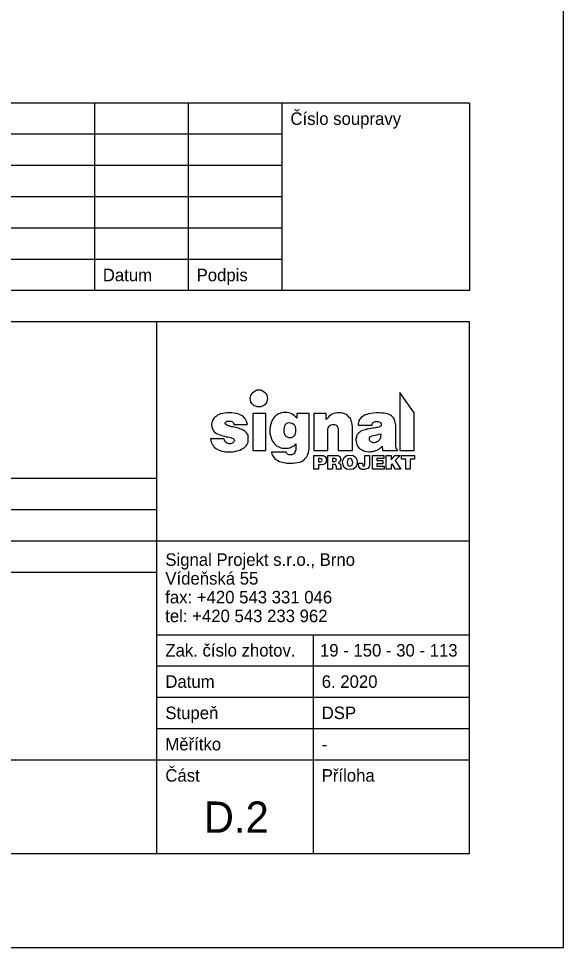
# Model space of a CAD drawing. Extents: x -790471 to -790261, y -988964 to -988667.
# Drawn here: x -790347.7 to -790260.6, y -988964.2 to -988815.7 of the extents above; entities that cross this region are included whole.
import ezdxf

# ---------------------------------------------------------------- set-up
doc = ezdxf.new("R2010")
doc.units = 0
for name, color, linetype in [('Info o rozpiskách', 7, 'Continuous'), ('popis', 7, 'Continuous'), ('Ramečky', 7, 'Continuous'), ('Rámečky-tisk', 7, 'Continuous'), ('Text', 7, 'Continuous'), ('Text barevný', 7, 'Continuous')]:
    doc.layers.add(name, color=color, linetype=linetype)

msp = doc.modelspace()

# ---------------------------------------------------------------- linework, layer by layer
at = {"layer": 'Info o rozpiskách'}
for points in [[(-790309.25, -988875.05), (-790308.98, -988875.07), (-790308.76, -988875.16), (-790308.54, -988875.29), (-790308.29, -988875.46), (-790308.15, -988875.66), (-790308.03, -988875.91), (-790307.94, -988876.17), (-790307.92, -988876.43), (-790307.94, -988876.69), (-790308.03, -988876.97), (-790308.15, -988877.21), (-790308.29, -988877.38), (-790308.54, -988877.59), (-790308.76, -988877.68), (-790308.98, -988877.77), (-790309.25, -988877.79), (-790309.54, -988877.77), (-790309.79, -988877.68), (-790310.05, -988877.59), (-790310.23, -988877.38), (-790310.4, -988877.21), (-790310.57, -988876.97), (-790310.65, -988876.69), (-790310.7, -988876.43), (-790310.65, -988876.17), (-790310.57, -988875.91), (-790310.4, -988875.66), (-790310.23, -988875.46), (-790310.05, -988875.29), (-790309.79, -988875.16), (-790309.54, -988875.07), (-790309.25, -988875.05)], [(-790300.48, -988885.53), (-790299.41, -988885.53), (-790299, -988885.57), (-790298.7, -988885.72), (-790298.52, -988885.96), (-790298.46, -988886.32), (-790298.65, -988886.84), (-790298.95, -988887.01), (-790299.38, -988887.06), (-790299.75, -988887.06), (-790299.75, -988887.75), (-790300.48, -988887.75), (-790300.48, -988885.53)], [(-790299.75, -988886.04), (-790299.75, -988886.54), (-790299.43, -988886.54), (-790299.25, -988886.48), (-790299.15, -988886.28), (-790299.23, -988886.11), (-790299.54, -988886.04), (-790299.75, -988886.04)], [(-790298.24, -988885.53), (-790297.16, -988885.53), (-790296.67, -988885.57), (-790296.35, -988885.72), (-790296.19, -988886.17), (-790296.3, -988886.52), (-790296.56, -988886.71), (-790296.24, -988886.93), (-790296.19, -988887.3), (-790296.19, -988887.47), (-790296.17, -988887.64), (-790296.11, -988887.7), (-790296.11, -988887.75), (-790296.86, -988887.75), (-790296.9, -988887.36), (-790297.03, -988887.01), (-790297.18, -988886.99), (-790297.4, -988886.97), (-790297.51, -988886.97), (-790297.51, -988887.75), (-790298.24, -988887.75), (-790298.24, -988885.53)], [(-790297.51, -988886.04), (-790297.51, -988886.48), (-790297.19, -988886.48), (-790296.93, -988886.41), (-790296.88, -988886.28), (-790296.95, -988886.11), (-790297.16, -988886.04), (-790297.51, -988886.04)], [(-790294.73, -988885.48), (-790294.23, -988885.55), (-790293.84, -988885.81), (-790293.63, -988886.19), (-790293.56, -988886.61), (-790293.63, -988887.08), (-790293.85, -988887.45), (-790294.23, -988887.72), (-790294.73, -988887.81), (-790295.25, -988887.72), (-790295.65, -988887.44), (-790295.83, -988887.06), (-790295.91, -988886.61), (-790295.83, -988886.17), (-790295.61, -988885.81), (-790295.23, -988885.55), (-790294.73, -988885.48)], [(-790294.73, -988886.02), (-790294.92, -988886.06), (-790295.05, -988886.17), (-790295.16, -988886.63), (-790295.05, -988887.12), (-790294.73, -988887.27), (-790294.38, -988887.08), (-790294.28, -988886.67), (-790294.4, -988886.2), (-790294.53, -988886.06), (-790294.73, -988886.02)], [(-790292.33, -988885.53), (-790291.6, -988885.53), (-790291.6, -988886.91), (-790291.67, -988887.34), (-790291.88, -988887.64), (-790292.46, -988887.81), (-790292.83, -988887.77), (-790293.11, -988887.62), (-790293.29, -988887.34), (-790293.37, -988886.95), (-790293.35, -988886.78), (-790292.7, -988886.78), (-790292.66, -988887.16), (-790292.51, -988887.27), (-790292.38, -988887.19), (-790292.33, -988887.01), (-790292.33, -988885.53)], [(-790291.13, -988885.53), (-790289.32, -988885.53), (-790289.32, -988886.04), (-790290.4, -988886.04), (-790290.4, -988886.37), (-790289.49, -988886.37), (-790289.49, -988886.89), (-790290.4, -988886.89), (-790290.4, -988887.23), (-790289.27, -988887.23), (-790289.27, -988887.75), (-790291.13, -988887.75), (-790291.13, -988885.53)], [(-790288.91, -988885.53), (-790288.16, -988885.53), (-790288.16, -988886.24), (-790287.53, -988885.53), (-790286.67, -988885.53), (-790287.49, -988886.37), (-790286.58, -988887.75), (-790287.46, -988887.75), (-790288, -988886.88), (-790288.16, -988887.04), (-790288.16, -988887.75), (-790288.91, -988887.75), (-790288.91, -988885.53)], [(-790286.47, -988885.53), (-790284.41, -988885.53), (-790284.41, -988886.11), (-790285.07, -988886.11), (-790285.07, -988887.75), (-790285.8, -988887.75), (-790285.8, -988886.11), (-790286.47, -988886.11), (-790286.47, -988885.53)]]:
    msp.add_lwpolyline(points, dxfattribs=at)
at = {"layer": 'popis'}
for points in [[(-790286.77, -988875.46), (-790286.77, -988884.73), (-790284.45, -988884.73), (-790284.45, -988878.7), (-790286.77, -988875.46)], [(-790313.29, -988880.61), (-790311.09, -988880.61), (-790311.15, -988880.42), (-790311.19, -988880.25), (-790311.24, -988880.09), (-790311.32, -988879.92), (-790311.41, -988879.77), (-790311.52, -988879.6), (-790311.63, -988879.45), (-790311.8, -988879.28), (-790311.97, -988879.19), (-790312.17, -988879.08), (-790312.4, -988878.98), (-790312.66, -988878.89), (-790312.94, -988878.83), (-790313.26, -988878.78), (-790313.61, -988878.74), (-790314, -988878.72), (-790314.4, -988878.74), (-790314.77, -988878.78), (-790315.09, -988878.85), (-790315.4, -988878.91), (-790315.66, -988879), (-790315.89, -988879.11), (-790316.07, -988879.25), (-790316.26, -988879.38), (-790316.43, -988879.53), (-790316.54, -988879.67), (-790316.65, -988879.82), (-790316.71, -988879.99), (-790316.78, -988880.18), (-790316.82, -988880.35), (-790316.86, -988880.48), (-790316.86, -988880.68), (-790316.8, -988880.98), (-790316.71, -988881.28), (-790316.62, -988881.5), (-790316.43, -988881.75), (-790316.26, -988881.88), (-790316.06, -988882.04), (-790315.81, -988882.16), (-790315.55, -988882.23), (-790315.29, -988882.32), (-790315.03, -988882.4), (-790314.77, -988882.47), (-790314.51, -988882.55), (-790314.25, -988882.58), (-790314.02, -988882.62), (-790313.8, -988882.68), (-790313.59, -988882.77), (-790313.39, -988882.85), (-790313.29, -988882.92), (-790313.22, -988883.01), (-790313.2, -988883.11), (-790313.24, -988883.28), (-790313.29, -988883.35), (-790313.33, -988883.44), (-790313.44, -988883.52), (-790313.57, -988883.59), (-790313.67, -988883.63), (-790313.8, -988883.67), (-790313.93, -988883.67), (-790314.06, -988883.67), (-790314.21, -988883.63), (-790314.38, -988883.57), (-790314.47, -988883.52), (-790314.6, -988883.39), (-790314.69, -988883.28), (-790314.77, -988883.09), (-790314.82, -988882.87), (-790317.01, -988882.87), (-790316.97, -988883.16), (-790316.9, -988883.42), (-790316.8, -988883.65), (-790316.69, -988883.83), (-790316.56, -988884.02), (-790316.41, -988884.19), (-790316.24, -988884.36), (-790316.06, -988884.49), (-790315.83, -988884.6), (-790315.61, -988884.71), (-790315.38, -988884.79), (-790315.14, -988884.86), (-790314.86, -988884.88), (-790314.62, -988884.94), (-790314.38, -988884.95), (-790314.06, -988884.95), (-790313.74, -988884.94), (-790313.43, -988884.94), (-790313.13, -988884.88), (-790312.83, -988884.82), (-790312.55, -988884.77), (-790312.31, -988884.67), (-790312.06, -988884.54), (-790311.86, -988884.45), (-790311.65, -988884.32), (-790311.47, -988884.15), (-790311.34, -988884), (-790311.2, -988883.83), (-790311.09, -988883.65), (-790311.02, -988883.42), (-790311, -988883.2), (-790311, -988882.98), (-790311, -988882.92), (-790311, -988882.87), (-790311, -988882.81), (-790311, -988882.75), (-790311, -988882.68), (-790311, -988882.62), (-790311, -988882.58), (-790311, -988882.55), (-790311.02, -988882.3), (-790311.11, -988882.12), (-790311.24, -988881.93), (-790311.39, -988881.8), (-790311.54, -988881.67), (-790311.73, -988881.52), (-790311.9, -988881.43), (-790312.12, -988881.35), (-790312.32, -988881.28), (-790312.55, -988881.2), (-790312.77, -988881.13), (-790312.98, -988881.09), (-790313.22, -988881.04), (-790313.43, -988880.98), (-790313.65, -988880.94), (-790313.84, -988880.89), (-790314.02, -988880.81), (-790314.19, -988880.78), (-790314.32, -988880.7), (-790314.45, -988880.66), (-790314.53, -988880.61), (-790314.64, -988880.53), (-790314.67, -988880.48), (-790314.67, -988880.4), (-790314.67, -988880.33), (-790314.64, -988880.25), (-790314.56, -988880.18), (-790314.49, -988880.14), (-790314.41, -988880.07), (-790314.28, -988880.07), (-790314.13, -988880.03), (-790314, -988880.03), (-790313.85, -988880.03), (-790313.72, -988880.07), (-790313.61, -988880.09), (-790313.5, -988880.14), (-790313.43, -988880.23), (-790313.39, -988880.33), (-790313.31, -988880.44), (-790313.29, -988880.61)], [(-790310.27, -988878.85), (-790310.27, -988884.73), (-790308.18, -988884.73), (-790308.18, -988878.85), (-790310.27, -988878.85)], [(-790303.24, -988878.83), (-790303.24, -988879.56), (-790303.41, -988879.36), (-790303.59, -988879.19), (-790303.8, -988879.02), (-790304.04, -988878.87), (-790304.28, -988878.76), (-790304.51, -988878.7), (-790304.75, -988878.67), (-790305.03, -988878.65), (-790305.29, -988878.67), (-790305.48, -988878.69), (-790305.74, -988878.72), (-790305.93, -988878.82), (-790306.15, -988878.87), (-790306.35, -988879.02), (-790306.58, -988879.13), (-790306.76, -988879.32), (-790306.91, -988879.51), (-790307.06, -988879.75), (-790307.19, -988879.99), (-790307.29, -988880.23), (-790307.4, -988880.55), (-790307.47, -988880.89), (-790307.51, -988881.26), (-790307.51, -988881.65), (-790307.51, -988881.97), (-790307.47, -988882.25), (-790307.4, -988882.51), (-790307.32, -988882.79), (-790307.23, -988883.03), (-790307.1, -988883.28), (-790306.93, -988883.48), (-790306.78, -988883.67), (-790306.62, -988883.83), (-790306.45, -988883.98), (-790306.22, -988884.11), (-790306, -988884.21), (-790305.78, -988884.3), (-790305.53, -988884.36), (-790305.29, -988884.39), (-790305.03, -988884.39), (-790304.81, -988884.39), (-790304.6, -988884.36), (-790304.34, -988884.32), (-790304.12, -988884.23), (-790303.91, -988884.13), (-790303.7, -988884), (-790303.56, -988883.87), (-790303.39, -988883.69), (-790303.39, -988884.23), (-790303.39, -988884.62), (-790303.46, -988884.88), (-790303.56, -988885.08), (-790303.63, -988885.23), (-790303.76, -988885.35), (-790303.91, -988885.38), (-790304.08, -988885.44), (-790304.26, -988885.44), (-790304.36, -988885.44), (-790304.49, -988885.42), (-790304.6, -988885.38), (-790304.69, -988885.35), (-790304.75, -988885.27), (-790304.84, -988885.2), (-790304.86, -988885.12), (-790304.9, -988885.03), (-790307.27, -988885.03), (-790307.21, -988885.33), (-790307.1, -988885.53), (-790306.97, -988885.76), (-790306.84, -988885.92), (-790306.67, -988886.13), (-790306.45, -988886.24), (-790306.24, -988886.33), (-790306, -988886.48), (-790305.78, -988886.56), (-790305.53, -988886.61), (-790305.31, -988886.67), (-790305.05, -988886.73), (-790304.84, -988886.75), (-790304.66, -988886.76), (-790304.43, -988886.78), (-790304.26, -988886.78), (-790303.85, -988886.76), (-790303.46, -988886.73), (-790303.09, -988886.67), (-790302.79, -988886.6), (-790302.49, -988886.5), (-790302.23, -988886.37), (-790302.03, -988886.22), (-790301.86, -988886.04), (-790301.69, -988885.83), (-790301.56, -988885.61), (-790301.45, -988885.37), (-790301.35, -988885.08), (-790301.32, -988884.79), (-790301.22, -988884.45), (-790301.22, -988884.1), (-790301.22, -988883.69), (-790301.22, -988878.83), (-790303.24, -988878.83)], [(-790300.5, -988878.85), (-790300.5, -988884.73), (-790298.26, -988884.73), (-790298.26, -988881.73), (-790298.26, -988881.41), (-790298.2, -988881.11), (-790298.11, -988880.94), (-790298.03, -988880.79), (-790297.9, -988880.7), (-790297.75, -988880.63), (-790297.57, -988880.61), (-790297.38, -988880.57), (-790297.19, -988880.61), (-790297.06, -988880.64), (-790296.9, -988880.7), (-790296.8, -988880.81), (-790296.73, -988880.94), (-790296.65, -988881.11), (-790296.62, -988881.37), (-790296.62, -988881.63), (-790296.62, -988884.73), (-790294.34, -988884.73), (-790294.34, -988881.19), (-790294.34, -988880.87), (-790294.36, -988880.57), (-790294.41, -988880.29), (-790294.51, -988880.03), (-790294.6, -988879.8), (-790294.71, -988879.6), (-790294.88, -988879.43), (-790294.99, -988879.26), (-790295.14, -988879.13), (-790295.31, -988879), (-790295.5, -988878.95), (-790295.68, -988878.85), (-790295.91, -988878.78), (-790296.09, -988878.74), (-790296.28, -988878.7), (-790296.5, -988878.7), (-790296.78, -988878.7), (-790297.06, -988878.78), (-790297.31, -988878.82), (-790297.57, -988878.95), (-790297.81, -988879.08), (-790298.05, -988879.26), (-790298.26, -988879.51), (-790298.5, -988879.77), (-790298.5, -988878.85), (-790300.5, -988878.85)], [(-790293.41, -988880.7), (-790291.19, -988880.7), (-790291.17, -988880.53), (-790291.13, -988880.4), (-790291.06, -988880.31), (-790290.96, -988880.23), (-790290.85, -988880.16), (-790290.7, -988880.12), (-790290.57, -988880.12), (-790290.42, -988880.12), (-790290.25, -988880.12), (-790290.09, -988880.14), (-790289.96, -988880.22), (-790289.88, -988880.25), (-790289.81, -988880.33), (-790289.73, -988880.4), (-790289.73, -988880.5), (-790289.69, -988880.59), (-790289.73, -988880.68), (-790289.75, -988880.79), (-790289.84, -988880.87), (-790289.94, -988880.94), (-790290.07, -988881.02), (-790290.25, -988881.06), (-790290.46, -988881.09), (-790290.66, -988881.13), (-790290.89, -988881.15), (-790291.13, -988881.19), (-790291.36, -988881.22), (-790291.6, -988881.26), (-790291.84, -988881.32), (-790292.08, -988881.35), (-790292.29, -988881.43), (-790292.51, -988881.47), (-790292.74, -988881.56), (-790292.96, -988881.67), (-790293.15, -988881.82), (-790293.31, -988881.91), (-790293.44, -988882.06), (-790293.54, -988882.21), (-790293.61, -988882.3), (-790293.67, -988882.47), (-790293.7, -988882.62), (-790293.74, -988882.79), (-790293.76, -988882.94), (-790293.76, -988883.11), (-790293.7, -988883.59), (-790293.56, -988883.98), (-790293.31, -988884.32), (-790293.05, -988884.53), (-790292.74, -988884.71), (-790292.38, -988884.84), (-790292.06, -988884.92), (-790291.73, -988884.94), (-790291.58, -988884.94), (-790291.45, -988884.92), (-790291.3, -988884.92), (-790291.13, -988884.88), (-790291.02, -988884.86), (-790290.85, -988884.84), (-790290.7, -988884.8), (-790290.57, -988884.77), (-790290.44, -988884.69), (-790290.31, -988884.62), (-790290.18, -988884.56), (-790290.03, -988884.47), (-790289.92, -988884.38), (-790289.81, -988884.26), (-790289.66, -988884.15), (-790289.55, -988884.06), (-790289.51, -988884.75), (-790287.12, -988884.75), (-790287.12, -988884.66), (-790287.25, -988884.53), (-790287.31, -988884.43), (-790287.36, -988884.34), (-790287.36, -988884.26), (-790287.4, -988884.15), (-790287.4, -988884.08), (-790287.4, -988883.97), (-790287.4, -988883.82), (-790287.4, -988880.94), (-790287.4, -988880.7), (-790287.46, -988880.46), (-790287.49, -988880.23), (-790287.53, -988880.01), (-790287.59, -988879.82), (-790287.64, -988879.67), (-790287.74, -988879.51), (-790287.9, -988879.34), (-790288.07, -988879.21), (-790288.24, -988879.1), (-790288.46, -988878.98), (-790288.71, -988878.89), (-790288.97, -988878.83), (-790289.3, -988878.8), (-790289.66, -988878.76), (-790290.07, -988878.7), (-790290.53, -988878.72), (-790291.02, -988878.76), (-790291.37, -988878.82), (-790291.73, -988878.87), (-790292.05, -988878.97), (-790292.29, -988879.06), (-790292.53, -988879.19), (-790292.74, -988879.32), (-790292.92, -988879.47), (-790293.05, -988879.62), (-790293.2, -988879.79), (-790293.28, -988879.97), (-790293.31, -988880.12), (-790293.37, -988880.31), (-790293.41, -988880.5), (-790293.41, -988880.7)], [(-790304.39, -988880.29), (-790304.19, -988880.33), (-790303.98, -988880.38), (-790303.8, -988880.48), (-790303.65, -988880.61), (-790303.56, -988880.79), (-790303.48, -988881), (-790303.41, -988881.26), (-790303.41, -988881.54), (-790303.41, -988881.78), (-790303.48, -988882.01), (-790303.54, -988882.23), (-790303.63, -988882.4), (-790303.74, -988882.51), (-790303.91, -988882.64), (-790304.08, -988882.7), (-790304.3, -988882.72), (-790304.53, -988882.7), (-790304.71, -988882.64), (-790304.9, -988882.51), (-790305.01, -988882.42), (-790305.1, -988882.23), (-790305.2, -988882.06), (-790305.23, -988881.84), (-790305.25, -988881.6), (-790305.23, -988881.33), (-790305.2, -988881.09), (-790305.16, -988880.87), (-790305.09, -988880.66), (-790304.99, -988880.53), (-790304.82, -988880.38), (-790304.64, -988880.33), (-790304.39, -988880.29)], [(-790289.81, -988882.06), (-790289.81, -988882.08), (-790289.81, -988882.14), (-790289.81, -988882.17), (-790289.84, -988882.44), (-790289.86, -988882.7), (-790289.96, -988882.88), (-790290.07, -988883.11), (-790290.22, -988883.28), (-790290.4, -988883.37), (-790290.61, -988883.46), (-790290.81, -988883.52), (-790290.98, -988883.52), (-790291.09, -988883.48), (-790291.21, -988883.42), (-790291.32, -988883.37), (-790291.43, -988883.29), (-790291.52, -988883.2), (-790291.6, -988883.11), (-790291.62, -988882.96), (-790291.58, -988882.72), (-790291.45, -988882.53), (-790291.22, -988882.42), (-790290.98, -988882.34), (-790290.66, -988882.27), (-790290.38, -988882.23), (-790290.09, -988882.14), (-790289.81, -988882.06)]]:
    msp.add_lwpolyline(points, dxfattribs=at)
at = {"layer": 'Ramečky'}
for p, q in [((-790275.59, -988829.19), (-790455.59, -988829.19)), ((-790335.59, -988829.19), (-790335.59, -988859.19)), ((-790320.59, -988829.19), (-790320.59, -988859.19)), ((-790305.59, -988829.19), (-790305.59, -988859.19)), ((-790275.59, -988829.19), (-790275.59, -988859.19)), ((-790305.59, -988834.19), (-790455.59, -988834.19)), ((-790305.59, -988839.19), (-790455.59, -988839.19)), ((-790305.59, -988844.19), (-790455.59, -988844.19)), ((-790305.59, -988849.19), (-790455.59, -988849.19)), ((-790305.59, -988854.19), (-790455.59, -988854.19)), ((-790275.59, -988859.19), (-790455.59, -988859.19)), ((-790275.59, -988864.19), (-790455.59, -988864.19)), ((-790325.59, -988949.19), (-790325.59, -988864.19)), ((-790275.59, -988949.19), (-790275.59, -988864.19)), ((-790455.59, -988889.19), (-790325.59, -988889.19)), ((-790455.59, -988894.19), (-790325.59, -988894.19)), ((-790455.59, -988899.19), (-790325.59, -988899.19)), ((-790455.59, -988904.19), (-790325.59, -988904.19)), ((-790325.59, -988914.19), (-790275.59, -988914.19)), ((-790325.59, -988919.19), (-790275.59, -988919.19)), ((-790325.59, -988924.19), (-790275.59, -988924.19)), ((-790325.59, -988929.19), (-790275.59, -988929.19)), ((-790455.59, -988934.19), (-790275.59, -988934.19)), ((-790455.59, -988949.19), (-790275.59, -988949.19))]:
    msp.add_line(p, q, dxfattribs=at)
for points in [[(-790325.59, -988899.19), (-790275.59, -988899.19)], [(-790300.59, -988914.19), (-790300.59, -988949.19)]]:
    msp.add_lwpolyline(points, dxfattribs=at)
at = {"layer": 'Rámečky-tisk'}
msp.add_lwpolyline([(-790470.59, -988964.19), (-790260.59, -988964.19), (-790260.59, -988667.19)], dxfattribs=at)

# ---------------------------------------------------------------- texts
at = {"layer": 'Text'}
for s, p in [('Číslo soupravy', (-790304.24, -988832.69)), ('Datum', (-790334.24, -988857.69)), ('Podpis', (-790319.24, -988857.69)), ('Signal Projekt s.r.o., Brno', (-790324.24, -988903.19)), ('Vídeňská 55', (-790324.24, -988906.19)), ('fax: +420 543 331 046', (-790324.26, -988909.19)), ('tel: +420 543 233 962', (-790324.26, -988912.19)), ('Zak. číslo zhotov.', (-790324.24, -988917.69)), ('19 - 150 - 30 - 113', (-790299.52, -988917.69)), ('Datum', (-790324.24, -988922.69)), ('6. 2020', (-790299.24, -988922.69)), ('Stupeň', (-790324.24, -988927.69)), ('DSP', (-790299.24, -988927.69)), ('Měřítko', (-790324.24, -988932.69)), ('-', (-790299.24, -988932.69)), ('Část', (-790324.24, -988937.69)), ('Příloha', (-790299.24, -988937.69))]:
    msp.add_text(s, height=2, dxfattribs=at).set_placement(p)
at = {"layer": 'Text barevný'}
msp.add_text('D.2', height=5, dxfattribs=at).set_placement((-790318.1, -988945.86))

doc.saveas('drawing.dxf')
